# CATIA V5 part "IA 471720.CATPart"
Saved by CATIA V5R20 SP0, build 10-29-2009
Part number: IA 471720
Revision: ANY
Definition: UNKNOWN
Nomenclature: IA 471720
Source: Unknown
Bounding box of the stored display mesh (mm): x -2.35 to 2.35, y -7.925 to 9.045, z -2.35 to 2.35
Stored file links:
  C:\Users\Utente\Desktop\IO LAVORO\3D X SITO CF\CUMSA\3D files IA\IA 471720\IA 471720.CATPart
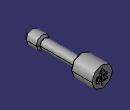
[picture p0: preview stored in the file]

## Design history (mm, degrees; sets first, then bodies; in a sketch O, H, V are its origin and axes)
Body1 "Cortar-Extruir3" (main body)
  Solid1: solid without history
